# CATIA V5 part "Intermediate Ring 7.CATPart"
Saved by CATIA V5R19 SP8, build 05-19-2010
Part number: Intermediate Ring 7
Bounding box of the stored display mesh (mm): x -20 to 20, y 390 to 586.988, z 598.002 to 641
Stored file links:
  G:\EU_thinkMotion\CFAO_2010\MMS_groupe3\MMS_groupe3\A reprendre\fovide\fovide\Intermediate Ring 7.CATPart
  G:\EU_thinkMotion\CFAO_2010\MMS_groupe3\MMS_groupe3\A reprendre\fovide\fovide\fovide.CATProduct
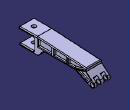
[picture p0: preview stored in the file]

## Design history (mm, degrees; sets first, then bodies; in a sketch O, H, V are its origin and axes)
Set1
  Plane1: linked copy from another document
  Point1 "Point.N": linked copy from another document
  Point2 "Point.M": linked copy from another document
  Line1 to Line3: linked copy from another document
Body1 (main body)
  Sketch1 on Plane1, origin (0, 0, 0), H (0, 1, 0), V (0, 0, 1)
    line L1 (390, 641) -> (437.237, 641)
    line L2 (437.237, 641) -> (564.2923, 633.7612)
    line L3 (564.2923, 633.7612) -> (564.2923, 626.9024)
    line L4 (564.2923, 626.9024) -> (584.4337, 610.4169)
    line L5 (577.0289, 598.6618) -> (536.1882, 617.8062)
    line L6 (536.1882, 617.8062) -> (454.3736, 617.8062)
    line L7 (454.3736, 617.8062) -> (438.8394, 599)
    line L8 (438.8394, 599) -> (391.2698, 599)
    line L9 (391.2698, 599) -> (391.2698, 605)
    line L10 (391.2698, 605) -> (430, 605)
    line L11 (430, 605) -> (430, 635)
    line L12 (430, 635) -> (390, 635)
    line L13 (390, 635) -> (390, 641)
    reference projected point E1 (410, 620) from Point1
    reference projected point E2 (410, 620) from Point1
    arc A1 centre (580, 605) radius 7 from (577.0289, 598.6618) to (584.4337, 610.4169) ccw
    point P15 (580, 605)
    reference projected point E3 (580, 605) from Point2
    length L12 = 40
    distance L13 E1 = 20
    length L11 = 30
    length L13 = 6
    length L9 = 6
    distance L12 E2 = 15
    radius A1 = 7
    horizontal: L1 H, L6 H, L8 H, L10 H, L12 H
    vertical: L3 V, L9 V, L11 V, L13 V
    tangency: L4 A1, A1 L5
    coincidence: P15 E3
  Pad1: profile Sketch1, direction (1, 0, 0), length 20, mirrored extent
  Sketch2 on face of Pad1 from Sketch1.L4, origin (0, 533.6453, 651.9867), H (-1, 0, 0), V (0, -0.7738, 0.6334)
    line L1 (4, -55.6316) -> (14, -55.6316)
    line L2 (14, -55.6316) -> (14, -84.6435)
    line L3 (14, -84.6435) -> (4, -84.6435)
    line L4 (4, -84.6435) -> (4, -55.6316)
    reference projected line E1 (0, -65.6316) -> (0, 75.4219) from Line1
    point P5 (-14, -55.6316)
    line L5 (-14, -55.6316) -> (-4, -55.6316)
    line L6 (-4, -55.6316) -> (-4, -84.5797)
    line L7 (-4, -84.5797) -> (-14, -84.5797)
    line L8 (-14, -84.5797) -> (-14, -55.6316)
    reference projected line E2 (150, -65.6316) -> (-150, -65.6316) from Line2
    reference projected line E3 (0, -65.6316) -> (0, 75.4219) from Line1
    length L1 = 10
    distance L4 E1 = 4
    distance L1 E2 = 10
    length L5 = 10
    distance L6 E3 = 4
    horizontal: L1 H, L3 H, L5 H, L7 H
    vertical: L2 V, L4 V, L6 V, L8 V
    coincidence: P5 L1
  Pocket1: profile Sketch2, direction (0, -0.6334, -0.7738), length 25
  Sketch3 on end face of Pad1, origin (20, 0, 0), H (0, 1, 0), V (0, 0, 1)
    line L1 (438.7051, 639.278) -> (475.6306, 637.1743)
    line L2 (475.6306, 637.1743) -> (475.6306, 619.0527)
    line L3 (475.6306, 619.0527) -> (438.7051, 619.0527)
    line L4 (438.7051, 619.0527) -> (438.7051, 639.278)
    reference projected line E1 (564.2923, 633.7612) -> (437.237, 641) from edge [face of Pad1 from Sketch1.L2 | end face of Pad1]
    point P5 (479.2982, 636.9653)
    line L5 (479.2982, 636.9653) -> (514.1881, 634.9775)
    line L6 (514.1881, 634.9775) -> (514.1881, 619.0527)
    point P7 (514.1881, 619.0527)
    line L7 (514.1881, 619.0527) -> (479.2982, 619.0527)
    line L8 (479.2982, 619.0527) -> (479.2982, 636.9653)
    point P9 (516.29, 634.8577)
    line L9 (516.29, 634.8577) -> (563.0499, 632.1936)
    line L10 (563.0499, 632.1936) -> (563.0499, 627.587)
    line L11 (563.0499, 627.587) -> (532.7192, 619.0527)
    point P12 (532.7192, 619.0527)
    line L12 (532.7192, 619.0527) -> (516.29, 619.0527)
    line L13 (516.29, 619.0527) -> (516.29, 634.8577)
    point P14 (538.2816, 619.0527)
    line L14 (538.2816, 619.0527) -> (563.0499, 626.0219)
    point P15 (563.0499, 626.0219)
    line L15 (563.0499, 626.0219) -> (578.3534, 613.3969)
    line L16 (578.3534, 613.3969) -> (569.526, 604.6199)
    line L17 (569.526, 604.6199) -> (538.2816, 619.0527)
    vertical: L2 V, L4 V, L6 V, L8 V, L10 V, L13 V
    horizontal: L3 H, L7 H, L12 H
    parallelism: L1 E1, L5 L1, L9 L5, L14 L11
    coincidence: P5 L1, P7 L3, P9 L1, P12 L3, P14 L3, P15 L10
  Pocket2: profile Sketch3, direction (-1, 0, 0), length 5
  Sketch4 on start face of Pad1, origin (-20, 0, 0), H (0, -1, 0), V (0, 0, 1)
    line L1 (-440.6666, 638.9078) -> (-480.361, 636.6463)
    line L2 (-480.361, 636.6463) -> (-480.361, 619.1391)
    line L3 (-480.361, 619.1391) -> (-440.6666, 619.1391)
    line L4 (-440.6666, 619.1391) -> (-440.6666, 638.9078)
    point P5 (-483.4491, 636.4703)
    line L5 (-483.4491, 636.4703) -> (-520.2281, 634.3749)
    line L6 (-520.2281, 634.3749) -> (-520.2281, 619.1391)
    point P7 (-520.2281, 619.1391)
    line L7 (-520.2281, 619.1391) -> (-483.4491, 619.1391)
    line L8 (-483.4491, 619.1391) -> (-483.4491, 636.4703)
    point P9 (-523.4012, 634.1941)
    line L9 (-523.4012, 634.1941) -> (-562.3438, 631.9754)
    line L10 (-562.3438, 631.9754) -> (-562.3438, 628.5091)
    line L11 (-562.3438, 628.5091) -> (-529.9014, 619.1391)
    point P12 (-529.9014, 619.1391)
    line L12 (-529.9014, 619.1391) -> (-523.4012, 619.1391)
    line L13 (-523.4012, 619.1391) -> (-523.4012, 634.1941)
    reference projected line E1 (-564.2923, 633.7612) -> (-437.237, 641) from edge [start face of Pad1 | face of Pad1 from Sketch1.L2]
    point P14 (-537.8141, 619.1391)
    line L14 (-537.8141, 619.1391) -> (-562.3438, 626.2238)
    point P15 (-562.3438, 626.2238)
    line L15 (-562.3438, 626.2238) -> (-577.1069, 614.1403)
    line L16 (-577.1069, 614.1403) -> (-567.1222, 605.4007)
    line L17 (-567.1222, 605.4007) -> (-537.8141, 619.1391)
    reference projected line E2 (-584.4337, 610.4169) -> (-564.2923, 626.9024) from edge [start face of Pad1 | face of Pad1 from Sketch1.L4]
    reference projected line E3 (-536.1882, 617.8062) -> (-577.0289, 598.6618) from edge [start face of Pad1 | face of Pad1 from Sketch1.L5]
    vertical: L2 V, L4 V, L6 V, L8 V, L10 V, L13 V
    horizontal: L3 H, L7 H, L12 H
    coincidence: P5 L1, P7 L3, P9 L1, P12 L3, P14 L3, P15 L10
    parallelism: L5 L1, L9 L1, L1 E1, L14 L11, L15 E2, L17 E3
  Pocket3: profile Sketch4, direction (1, 0, 0), length 5
  Fillet1: radius 2, on end face of Pocket2 (x4); end face of Pocket3 (x4)
  Fillet2: radius 2, on face of Pad1 from Sketch1.L10; face of Pad1 from Sketch1.L9; face of Pad1 from Sketch1.L11; face of Pad1 from Sketch1.L12; face of Pad1 from Sketch1.L13; face of Pad1 from Sketch1.L8; face of Pad1 from Sketch1.L1; face of Pad1 from Sketch1.L2
  Sketch5 on face of Pad1 from Sketch1.L1, origin (0, 410, 641), H (1, 0, 0), V (0, 1, 0)
    point P1 (0, 0)
    intersected point E1 (0, 0) from Line3
    coincidence: E1 P1
  Hole1: placed by Sketch5, at (0, 410, 641) direction (0, 0, -1), diameter 10, through (limit type 3)
  Sketch6 on end face of Pad1, origin (20, 580, 605), H (0, 1, 0), V (0, 0, 1)
    point P1 (0, 0)
    intersected point E1 (0, 0) from Line2
    coincidence: E1 P1
  Hole2: placed by Sketch6, at (20, 580, 605) direction (-1, 0, 0), diameter 10, through (limit type 3)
